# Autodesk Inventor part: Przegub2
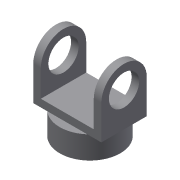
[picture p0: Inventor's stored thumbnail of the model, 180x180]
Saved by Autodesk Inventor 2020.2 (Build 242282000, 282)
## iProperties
Created: 2005-10
Part Number: Przegub2
Document SubType Name: Modeling
Designer: F.Stasiak
Material: Ogólny
Density: 1 g/cm^3
Appearance: Domyślna
Manager: www.cadconsulting.pl
Company: Fabian Stasiak CAD Consulting
Author: F.Stasiak
Subject: Zbiór ćwiczeń. Autodesk Inventor 2020. Kurs podstawowy
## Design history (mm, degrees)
sketch "Szkic1"
  geometry: C1 r 40 at (0, 0); 1 further point
  constraints: 1 centre point, 1 coincident
  dimensions: "d0" = 80 diameter of C1
extrude "Wyciągnięcie proste1" new body sketch "Szkic1" distance "d1" = 30; taper "d2" = 0 deg
sketch "Szkic2"
  geometry: L1 (-45, 30)-(45, 30); L2 (45, 30)-(45, -30); L3 (45, -30)-(-45, -30); L4 (-45, -30)-(-45, 30); L5 (0, 30)-(0, -30); C1 r 40 at (0, 0) reference; 1 further point
  constraints: 10 end point, 3 midpoint, 2 parallel, 1 coincident, 1 horizontal, 1 perpendicular
  dimensions: "d3" = 60 distance of L1.end L2.end; "d4" = 90 distance of L1.start L1.end
extrude "Wyciągnięcie proste2" join sketch "Szkic2" distance "d5" = 75; taper "d6" = 0 deg
fillet "Zaokrąglenie1" dims "d7" = 30
sketch "Szkic3"
  geometry: L1 (0, 45)-(90, 45) reference; L2 (0, 0)-(0, 45) reference; L3 (18.542, 0)-(0, 0) reference; L4 (71.458, 0)-(18.542, 0) reference; L5 (90, 0)-(71.458, 0) reference; L6 (90, 0)-(90, 45) reference; L7 (0, 75)-(90, 75) reference; L8 (10, 75)-(80, 75); L9 (80, 75)-(80, 10); L10 (80, 10)-(10, 10); L11 (10, 10)-(10, 75); L12 (90, 75)-(90, 45) reference; L13 (0, 45)-(0, 75) reference
  constraints: 8 end point, 2 parallel, 1 collinear, 1 horizontal, 1 perpendicular
  dimensions: "d8" = 10 distance between parallel lines of L10 L4; "d9" = 10 distance between parallel lines of L12 L9; "d10" = 10 distance between parallel lines of L13 L11
extrude "Wyciągnięcie proste3" cut sketch "Szkic3" extent not by distance; stored distance "d11" = 70; taper "d12" = 0 deg
sketch "Szkic4"
  geometry: L1 (0, 60)-(45, 60) reference; L2 (0, 0)-(0, 60) reference; L3 (0, 0)-(45, 0) reference; A1 r 30 centre (45, 30) between (45, 0) and (45, 60) reference
hole "Otwór1" sketch "Szkic4" at (45, 30) diameter "d13" = 40; stored, may be unused: countersink angle "d17" = 90 deg, drill point angle "d19" = 118 deg; dims "d14" = 6, "d15" = 4, "d16" = 2, "d18" = 8
node "Bryła1"
node "Korpusy bryłowe"
node "Korpusy powierzchniowe"
node "Pętla rzutowana1"
node "Pętla rzutowana2"
